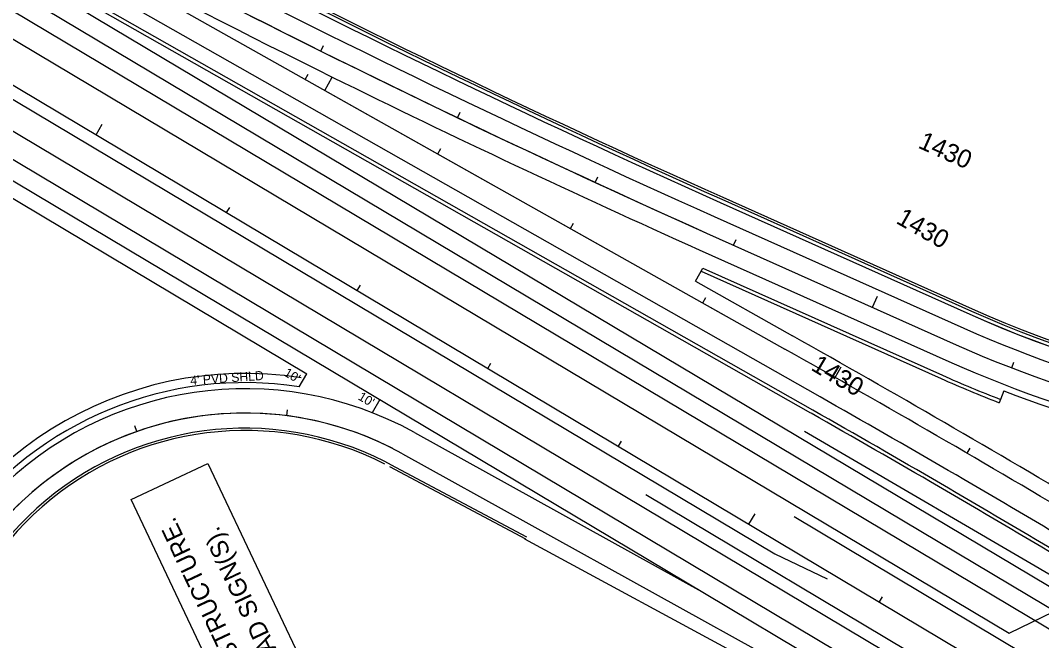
# Model space of a CAD drawing. Extents: x 2338610 to 2351914, y 366540 to 376484.
# Drawn here: x 2348627 to 2349299, y 368124 to 368532 of the extents above; entities that cross this region are included whole.
import ezdxf

# ---------------------------------------------------------------- set-up
doc = ezdxf.new("R2010")
doc.units = 0
for name, color, linetype in [('RD_HC_Cl', 7, 'Continuous'), ('RD_HC_CL_Rel', 7, 'Continuous'), ('RD_PD_Final_LnLine', 7, 'Continuous'), ('RD_PD_Final_TrvlWay', 7, 'Continuous'), ('RD_PD_FOC', 7, 'Continuous'), ('RD_PD_GR', 7, 'Continuous'), ('RD_PD_GrRail', 7, 'Continuous'), ('RD_PD_MedBWall', 7, 'Continuous'), ('RD_PD_MedGR', 7, 'Continuous'), ('RD_PD_NOISE-WALL-GM', 7, 'Continuous'), ('RD_PD_PaveShd', 7, 'Continuous'), ('RD_PD_WallCut', 7, 'Continuous'), ('TR SN EXTRUDED PANEL SIGNS- MOUNTED OVERHEAD', 7, 'Continuous'), ('TR SN UNASSIGNED 7', 7, 'Continuous')]:
    doc.layers.add(name, color=color, linetype=linetype)

msp = doc.modelspace()

# ---------------------------------------------------------------- linework, layer by layer
at = {"layer": 'RD_HC_Cl'}
msp.add_line((2346281.57, 369885.43), (2351112.4, 367003.22), dxfattribs=at)
at = {"layer": 'RD_HC_CL_Rel'}
for p, q in [((2348500.93, 368669.16), (2349129.79, 368315.43)), ((2349078.31, 368391.71), (2349242.47, 368318.22))]:
    msp.add_line(p, q, dxfattribs=at)
for centre, radius, start, end in [((2351938.58, 374780.68), 7000, 240.642806, 245.882475), ((2344717.52, 360471.2), 9000, 59.178507, 60.642806), ((2349557.92, 369022.83), 772, 245.88247, 289.58804), ((2348774.65, 368059.29), 214.01, 62.97341, 174.06692)]:
    msp.add_arc(centre, radius, start, end, dxfattribs=at)
at = {"layer": 'RD_PD_Final_LnLine'}
for p, q in [((2348620.92, 368538.62), (2349820.78, 367822.75)), ((2348577.88, 368466.48), (2349209.46, 368089.66)), ((2349078.31, 368391.71), (2349242.47, 368318.22)), ((2349076.83, 368154.82), (2349196.76, 368083.27))]:
    msp.add_line(p, q, dxfattribs=at)
for centre, radius, start, end in [((2351938.58, 374780.68), 7000, 239.178507, 245.882475), ((2351938.58, 374780.68), 7012, 240.642806, 243.703137), ((2349557.92, 369022.83), 772, 245.88247, 289.58804), ((2351783.35, 362853.29), 5729.58, 109.588035, 115.940729), ((2351783.35, 362853.29), 5717.58, 109.58804, 115.94073), ((2351783.35, 362853.29), 5705.58, 109.58804, 115.94073), ((2351783.35, 362853.29), 5693.58, 110.25944, 115.94073)]:
    msp.add_arc(centre, radius, start, end, dxfattribs=at)
at = {"layer": 'RD_PD_Final_TrvlWay'}
for p, q in [((2349153.03, 368283.92), (2348521.76, 368642.31)), ((2348626.93, 368549.01), (2349813.16, 367841.27)), ((2348827.21, 368485.63), (2348832.11, 368494.34)), ((2348827.21, 368485.63), (2349129.79, 368315.43)), ((2348571.59, 368456.26), (2349076.83, 368154.82)), ((2349083.21, 368402.66), (2349247.38, 368329.17)), ((2349073.41, 368380.76), (2349237.57, 368307.27)), ((2348863.44, 368282.13), (2348858.32, 368273.54)), ((2348886.11, 368260.49), (2349076.83, 368154.82)), ((2348878.36, 368246.49), (2349178.28, 368080.32))]:
    msp.add_line(p, q, dxfattribs=at)
for centre, radius, start, end in [((2351938.58, 374780.68), 6988, 239.178507, 245.882475), ((2351938.58, 374780.68), 7012, 243.703137, 245.882475), ((2349557.92, 369022.83), 760, 245.88247, 289.58804), ((2344717.52, 360471.2), 9000, 59.178507, 60.642806), ((2349557.92, 369022.83), 784, 245.88247, 289.58804), ((2348774.64, 368059.31), 230, 61.0108, 285.1623), ((2344717.52, 360471.2), 8984, 59.178507, 60.415096), ((2348774.64, 368059.31), 214, 61.0108, 285.16043), ((2351783.35, 362853.29), 5681.58, 111.03168, 115.94073)]:
    msp.add_arc(centre, radius, start, end, dxfattribs=at)
at = {"layer": 'RD_PD_FOC'}
msp.add_line((2348869.75, 368238.08), (2348959.09, 368190.55), dxfattribs=at)
msp.add_arc((2348774.64, 368059.31), 202.5, 62.97341, 267.67657, dxfattribs=at)
at = {"layer": 'RD_PD_GR'}
msp.add_line((2349071, 368359.97), (2349134.69, 368324.14), dxfattribs=at)
for centre, radius, start, end in [((2344717.52, 360471.2), 9010, 59.178507, 60.642806), ((2348774.64, 368059.31), 240, 81.15571, 162.94062)]:
    msp.add_arc(centre, radius, start, end, dxfattribs=at)
at = {"layer": 'RD_PD_GrRail'}
for p, q in [((2349142.77, 368261.41), (2349346.2, 368142.48)), ((2349038.24, 368219.76), (2349234.87, 368102.45)), ((2349286.8, 368114.85), (2349135.79, 368204.98)), ((2349176.03, 368072.84), (2348958.64, 368190.22))]:
    msp.add_line(p, q, dxfattribs=at)
at = {"layer": 'RD_PD_MedBWall'}
for p, q in [((2349087.3, 368411.79), (2349251.46, 368338.3)), ((2349088.25, 368413.92), (2349252.42, 368340.43))]:
    msp.add_line(p, q, dxfattribs=at)
for centre, radius, start, end in [((2351938.58, 374780.68), 6978, 239.178507, 245.882475), ((2351938.58, 374780.68), 6975.67, 239.178507, 245.882475), ((2349557.92, 369022.83), 750, 245.88247, 274.60618), ((2349557.92, 369022.83), 747.67, 245.88247, 274.60835)]:
    msp.add_arc(centre, radius, start, end, dxfattribs=at)
at = {"layer": 'RD_PD_MedGR'}
for p, q in [((2347144.89, 369361.04), (2349123.23, 368180.7)), ((2349123.23, 368180.7), (2349157.68, 368164.3))]:
    msp.add_line(p, q, dxfattribs=at)
at = {"layer": 'RD_PD_NOISE-WALL-GM'}
msp.add_line((2349088.87, 368415.29), (2349253.03, 368341.8), dxfattribs=at)
for centre, radius, start, end in [((2351938.58, 374780.68), 6974.17, 242.512616, 245.882475), ((2349557.92, 369022.83), 746.17, 245.88247, 274.84011)]:
    msp.add_arc(centre, radius, start, end, dxfattribs=at)
at = {"layer": 'RD_PD_PaveShd'}
for p, q in [((2348633, 368559.35), (2349320.08, 368149.43)), ((2348612.75, 368524.86), (2349277.31, 368128.37)), ((2348586.11, 368480.2), (2349221.38, 368101.18)), ((2348552.32, 368456.11), (2348815.37, 368299.17)), ((2349087.3, 368411.79), (2349251.46, 368338.3)), ((2349071, 368359.97), (2349075.9, 368368.69)), ((2349075.9, 368368.69), (2349233.48, 368298.14)), ((2349071, 368359.97), (2349134.69, 368324.14)), ((2348810.25, 368290.58), (2348815.37, 368299.17)), ((2349273.69, 368287.88), (2349271.53, 368282.28)), ((2348870.46, 368239.4), (2348959.8, 368191.87)), ((2349277.31, 368128.37), (2349320.08, 368149.43))]:
    msp.add_line(p, q, dxfattribs=at)
for centre, radius, start, end in [((2351938.58, 374780.68), 6978, 239.178507, 245.882475), ((2349557.92, 369022.83), 750, 245.88247, 273.68943), ((2344717.52, 360471.2), 9010, 59.178507, 60.642806), ((2349557.92, 369022.83), 794, 245.88247, 248.85722), ((2348774.64, 368059.31), 234, 81.2484, 268.00355), ((2349557.92, 369022.83), 788, 248.85722, 287.713), ((2344717.52, 360471.2), 8974, 59.178507, 60.415096), ((2348774.64, 368059.31), 204, 61.0108, 267.6974)]:
    msp.add_arc(centre, radius, start, end, dxfattribs=at)
at = {"layer": 'RD_PD_WallCut'}
for p, q in [((2349148.1, 368275.22), (2348628.23, 368570.36)), ((2349148.1, 368275.22), (2348628.23, 368570.36)), ((2349146.94, 368273.19), (2348627.08, 368568.34)), ((2349075.9, 368368.69), (2349233.48, 368298.14)), ((2349074.75, 368366.65), (2349232.53, 368296.01)), ((2349271.53, 368282.28), (2349270.69, 368280.1))]:
    msp.add_line(p, q, dxfattribs=at)
for centre, radius, start, end in [((2349557.92, 369022.83), 796.33, 245.88247, 248.85722), ((2349557.92, 369022.83), 794, 245.88247, 248.85722), ((2344717.52, 360471.2), 8974, 59.178507, 60.415096), ((2344717.52, 360471.2), 8971.67, 59.178507, 60.415096)]:
    msp.add_arc(centre, radius, start, end, dxfattribs=at)
at = {"layer": 'TR SN EXTRUDED PANEL SIGNS- MOUNTED OVERHEAD'}
msp.add_lwpolyline([(2348842.8, 367914.48), (2348699.83, 368216.35), (2348750.13, 368240.18), (2348893.11, 367938.31)], close=True, dxfattribs=at)
at = {"layer": 'TR SN UNASSIGNED 7'}
for p, q in [((2348824.62, 368511.45), (2348826.4, 368515.03)), ((2348814.35, 368492.86), (2348816.31, 368496.35)), ((2348914.49, 368467.6), (2348916.22, 368471.21)), ((2348676.74, 368456.4), (2348680.84, 368463.27)), ((2348901.51, 368443.83), (2348903.47, 368447.32)), ((2349004.99, 368425.05), (2349006.66, 368428.68)), ((2348762.62, 368405.17), (2348764.67, 368408.6)), ((2348988.67, 368394.81), (2348990.63, 368398.3)), ((2349096.07, 368383.76), (2349097.7, 368387.41)), ((2348848.49, 368353.93), (2348850.54, 368357.37)), ((2349075.82, 368345.78), (2349077.78, 368349.27)), ((2349187.34, 368342.9), (2349190.61, 368350.2)), ((2348934.37, 368302.69), (2348936.42, 368306.13)), ((2349162.94, 368296.69), (2349166.89, 368303.64)), ((2349279.01, 368302.97), (2349280.45, 368306.7)), ((2348802.14, 368271.53), (2348802.65, 368275.49)), ((2348703.59, 368261.16), (2348702.26, 368264.93)), ((2349020.25, 368251.46), (2349022.3, 368254.89)), ((2349249.62, 368246.81), (2349251.63, 368250.27)), ((2349106.13, 368200.22), (2349110.22, 368207.09)), ((2349192, 368148.99), (2349194.05, 368152.42))]:
    msp.add_line(p, q, dxfattribs=at)

# ---------------------------------------------------------------- texts
at = {"layer": 'RD_PD_Final_TrvlWay'}
for s, rotation, p in [("4' PVD SHLD", 3.96983, (2348738.94, 368291.77)), ("10'", 329.17851, (2348799.78, 368298.24)), ("10'", 329.17851, (2348848.56, 368282.53))]:
    msp.add_text(s, height=6, rotation=rotation, dxfattribs=at).set_placement(p)
at = {"layer": 'TR SN EXTRUDED PANEL SIGNS- MOUNTED OVERHEAD'}
for s, p in [('ERECT NEW CANTILEVER STRUCTURE.', (2348857.44, 367932.65)), ('INSTALL NEW OVERHEAD SIGN(S).', (2348870.25, 367960.36))]:
    msp.add_text(s, height=11.7187, rotation=115.34433, dxfattribs=at).set_placement(p)
at = {"layer": 'TR SN UNASSIGNED 7'}
for rotation, p in [(335.88247, (2349216.74, 368448.07)), (330.40039, (2349202.26, 368398.56)), (329.17851, (2349146.28, 368302.02))]:
    msp.add_text('1430', height=12, rotation=rotation, dxfattribs=at).set_placement(p)

doc.saveas('drawing.dxf')
